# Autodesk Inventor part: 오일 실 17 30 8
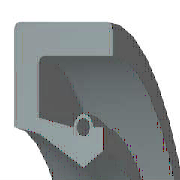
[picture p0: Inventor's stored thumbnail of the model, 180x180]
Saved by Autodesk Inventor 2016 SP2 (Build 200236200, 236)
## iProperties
IsCustomPart: 1
Created: 2012-02
Part Number: 오일 실 17 30 8
Material: 고무
Description: 오일-실
Document SubType Name: Modeling
Standard: KS B 2804
Designer: mduedu
Standards Organization: KS
Language: ko-KR
Size Designation: S - 17 30 8
Categories: <MemberInstance><Categories><Category DisplayName="샤프트 부품" InternalName="7f7aeb1f-a693-4053-b835-cee3144e0d98" Mnemonic="SHFT"><Category DisplayName="실링" Intern
Density: 0.93 g/cm^3
Appearance: 고무 - 검은색 - 버전 1.1
Author: mduedu
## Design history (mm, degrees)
revolve "본체" stored, may be unused: angle "d17" = 90 deg
revolve "스프링1" stored, may be unused: angle "d18" = 90 deg
body "Solid1"
sketch "스케치1"
  geometry: L1 (0, 15)-(8, 15); L2 (8, 15)-(8, 13.75); L3 (8, 13.75)-(1.75, 13.75); L4 (0, 15)-(0, 10.6); L5 (0, 10.6)-(1.75, 10.25); L6 (1.75, 10.25)-(4.9, 8.5); L7 (4.9, 8.5)-(0, 8.5); L8 (6.3, 9.375)-(6.3, 10.6); L9 (0, 0)-(9.586, 0) reference; L10 (4.9, 8.5)-(6.3, 9.375); L11 (0, 18)-(0, -3) reference; L12 (-1.917, 0)-(11.503, 0) reference; L13 (4.2, 10.6)-(1.75, 11.09); L14 (1.75, 11.09)-(1.75, 13.75); L15 (6.3, 10.6)-(5.6, 10.6); C1 r 0.455 at (4.9, 10.6); A1 r 0.7 centre (4.9, 10.6) between (5.6, 10.6) and (4.2, 10.6)
  constraints: 26 end point, 5 horizontal alignment, 4 perpendicular, 2 centre point, 2 collinear, 2 horizontal, 2 parallel, 2 point on circle, 2 point on line, 2 vertical alignment, 1 coincident
  dimensions: "d0" = 30 diameter of L1 L9 (= SD2); "d1" = 18.75 diameter of L8.start L9 (= ABDM); "d2" = 1.25 distance of L1.end L2.end (computed from SD); "d3" = 0.91 diameter of C1 (= SPDI); "d4" = 1.4 diameter of A1 (= SPDA); "d5" = 17 diameter of L6.end L9 (= NND); "d6" = 20.5 diameter of L5.end L9 (= TKDM); "d7" = 21.2 diameter of L4.end L9 (= HLDM); "d8" = 4.9 distance from line of C1.centre L4 (= SPDST); "d9" = 6.3 distance between parallel lines of L8 L4 (= SDI); "d10" = 8 distance between parallel lines of L2 L4 (= SWDT); "d12" = 1.75 distance between parallel lines of L14 L4 (= SD)
fillet "모깎기1" dims "d11" = 0.5 (= RR)
other parameters: "SD2" = 30 [user parameter; used in 1 equation term], "SWDT" = 8 [user parameter; used in 1 equation term], "RR" = 0.5 [user parameter; used in 1 equation term], "SD" = 1.75 [user parameter; used in 2 equation terms], "NND" = 17 [user parameter; used in 1 equation term], "SPDA" = 1.4 [user parameter; used in 1 equation term], "SPDI" = 0.91 [user parameter; used in 1 equation term], "TKDM" = 20.5 [user parameter; used in 1 equation term], "HLDM" = 21.2 [user parameter; used in 1 equation term], "ABDM" = 18.75 [user parameter; used in 1 equation term], "SDI" = 6.3 [user parameter; used in 1 equation term], "SPDST" = 4.9 [user parameter; used in 1 equation term], "d13" = 0, "d14" = 0, "d15" = 0, "LAB" = 0.35 [user parameter]
